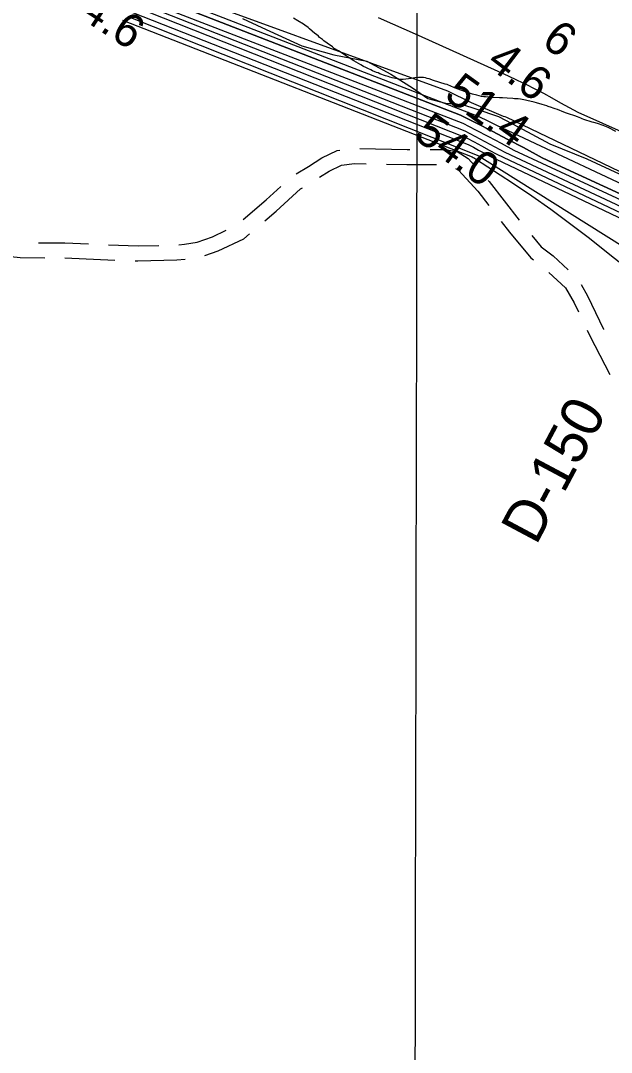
# Model space of a CAD drawing. Extents: x 3192986 to 3230865, y 867483 to 892886.
# Drawn here: x 3212086 to 3213265, y 874442 to 876501 of the extents above; entities that cross this region are included whole.
import ezdxf

# ---------------------------------------------------------------- set-up
doc = ezdxf.new("R2010")
doc.units = 0
for name, color, linetype in [('V-GRID-MAJR', 7, 'Continuous'), ('V-RIVR-EDGE', 7, 'Continuous'), ('V-RIVR-RANG', 7, 'Continuous'), ('V-RIVR-RANG-IDEN', 7, 'Continuous'), ('V-ROAD-CNTR', 7, 'Continuous'), ('V-SITE-VEGE', 7, 'Continuous'), ('V-TOPO-DPTH', 7, 'Continuous'), ('V-TOPO-MAJR', 7, 'Continuous'), ('V-TOPO-MINR', 7, 'Continuous'), ('V-TOPO-WATR', 7, 'Continuous')]:
    doc.layers.add(name, color=color, linetype=linetype)

msp = doc.modelspace()

# ---------------------------------------------------------------- linework, layer by layer
at = {"layer": 'V-GRID-MAJR'}
msp.add_spline([(3212870.4, 872891.2), (3212881.9, 878950.4), (3212893.3, 885013.1), (3212904.8, 891075.8), (3212904.8, 891079.2)], degree=3, dxfattribs=at)
at = {"layer": 'V-RIVR-EDGE'}
msp.add_lwpolyline([(3212528.3, 876504.7), (3212567.4, 876487.2), (3212646.8, 876450.5), (3212710.7, 876432.6), (3212776.7, 876420.2), (3212824.9, 876394), (3212867.9, 876366.5), (3212898.7, 876345.1), (3212933.9, 876336.4), (3212967.3, 876333.7), (3212994.3, 876324.9), (3213039.4, 876309.2), (3213078.5, 876288.6), (3213141.9, 876254.6), (3213215.7, 876224.8), (3213280, 876195.1)], dxfattribs=at)
at = {"layer": 'V-ROAD-CNTR'}
msp.add_line((3212174.2, 876027.3), (3212274.1, 876023.1), dxfattribs=at)
for points in [[(3212635.7, 876194.9), (3212660.3, 876209.8), (3212686.8, 876226.8), (3212717.7, 876241.9), (3212723, 876242.5)], [(3212762.8, 876245.4), (3212856.9, 876243.4), (3212862.8, 876243.4)], [(3212902.8, 876243.7), (3212931.7, 876243.8), (3212957.2, 876239.6), (3212979, 876225.5), (3212992.1, 876211.3)], [(3212682.2, 876188.2), (3212701.5, 876200.6), (3212726.2, 876212.6), (3212752.4, 876215.6), (3212775.6, 876215.1)], [(3212815.6, 876214.3), (3212856.7, 876213.4), (3212915.6, 876213.7)], [(3212953.9, 876206), (3212959.6, 876202.3), (3212998.2, 876160.3), (3213020.3, 876131.7)], [(3213019.1, 876181.8), (3213021.1, 876179.7), (3213080.5, 876102.9)], [(3212529.6, 876103.8), (3212575.6, 876143.1), (3212604.8, 876169.7)], [(3212573, 876101.4), (3212595.5, 876120.6), (3212644, 876164.8), (3212648.1, 876167.3)], [(3213044.8, 876100.1), (3213061.2, 876078.9), (3213103.9, 876027.5), (3213109, 876023.7)], [(3212401.3, 876053.7), (3212412.6, 876054.6), (3212437.8, 876058.7), (3212468.5, 876069.3), (3212496.2, 876082.4)], [(3212453.1, 876032.2), (3212479.9, 876041.5), (3212531, 876065.6), (3212542.6, 876075.5)], [(3213105.9, 876072), (3213124.7, 876049.4), (3213148.6, 876031.4), (3213178.5, 876003.8)], [(3212121.5, 876057.7), (3212173.9, 876057.3), (3212221.5, 876055.4)], [(3212261.4, 876053.7), (3212320.3, 876051.2), (3212361.4, 876052.3)], [(3212034.5, 876033.1), (3212085, 876027.9), (3212134.2, 876027.6)], [(3212314.1, 876021.5), (3212320, 876021.2), (3212397.2, 876023.2), (3212414, 876024.7)], [(3213140, 875998.5), (3213173.3, 875967.7), (3213190.5, 875937.4), (3213199, 875919.6)], [(3213204.3, 875973.9), (3213217.2, 875951.3), (3213248.8, 875884.8), (3213249, 875884.5)], [(3213216.2, 875883.4), (3213222, 875871.5), (3213261.9, 875794.5)]]:
    msp.add_lwpolyline(points, dxfattribs=at)
at = {"layer": 'V-SITE-VEGE'}
for p, q in [((3212639.1, 876500.7), (3212630.2, 876505.5)), ((3212650.6, 876493.6), (3212639.1, 876500.7)), ((3212653.2, 876491.6), (3212650.6, 876493.6)), ((3212659.5, 876487.1), (3212653.2, 876491.6)), ((3212662.5, 876484.7), (3212659.5, 876487.1)), ((3212673.2, 876475.4), (3212662.5, 876484.7)), ((3212676.1, 876473), (3212673.2, 876475.4)), ((3212680.1, 876469.6), (3212676.1, 876473)), ((3212682.5, 876467.4), (3212680.1, 876469.6)), ((3212688.4, 876462.9), (3212682.5, 876467.4)), ((3212690.8, 876460.7), (3212688.4, 876462.9)), ((3212697.3, 876456), (3212690.8, 876460.7)), ((3212700.5, 876454), (3212697.3, 876456)), ((3212703.5, 876451.6), (3212700.5, 876454)), ((3212708, 876448.2), (3212703.5, 876451.6)), ((3212711.4, 876445.4), (3212708, 876448.2)), ((3212719.9, 876440.3), (3212711.4, 876445.4)), ((3212741.5, 876426.6), (3212719.9, 876440.3)), ((3212750.6, 876420.7), (3212741.5, 876426.6)), ((3212764.5, 876412.4), (3212750.6, 876420.7)), ((3212770.2, 876409.4), (3212764.5, 876412.4)), ((3212774.6, 876407.4), (3212770.2, 876409.4)), ((3212778.9, 876405.2), (3212774.6, 876407.4)), ((3212784.9, 876402.7), (3212778.9, 876405.2)), ((3212788.2, 876400.9), (3212784.9, 876402.7)), ((3212796.1, 876397.5), (3212788.2, 876400.9)), ((3212799.3, 876396.3), (3212796.1, 876397.5)), ((3212802.3, 876394.9), (3212799.3, 876396.3)), ((3212814, 876390.6), (3212802.3, 876394.9)), ((3212819.3, 876389.2), (3212814, 876390.6)), ((3212822.7, 876388), (3212819.3, 876389.2)), ((3212827, 876386.8), (3212822.7, 876388)), ((3212837.1, 876384.4), (3212827, 876386.8)), ((3212840.5, 876384), (3212837.1, 876384.4)), ((3212845.5, 876383.6), (3212840.5, 876384)), ((3212849.4, 876383.6), (3212845.5, 876383.6)), ((3212854.8, 876384), (3212849.4, 876383.6)), ((3212865.1, 876385), (3212854.8, 876384)), ((3212872.8, 876386.4), (3212865.1, 876385)), ((3212879.7, 876387.4), (3212872.8, 876386.4)), ((3212884.7, 876387.4), (3212879.7, 876387.4)), ((3212890, 876387), (3212884.7, 876387.4)), ((3212893.6, 876386.4), (3212890, 876387)), ((3212896.9, 876385.6), (3212893.6, 876386.4)), ((3212901.1, 876384.4), (3212896.9, 876385.6)), ((3212910, 876381.6), (3212901.1, 876384.4)), ((3212933, 876374.1), (3212910, 876381.6)), ((3212937, 876373.1), (3212933, 876374.1)), ((3212945.7, 876369.4), (3212937, 876373.1)), ((3212948.8, 876368.2), (3212945.7, 876369.4)), ((3212951.8, 876366.8), (3212948.8, 876368.2)), ((3212958.9, 876364), (3212951.8, 876366.8)), ((3212962.1, 876363), (3212958.9, 876364)), ((3212966.5, 876361.2), (3212962.1, 876363)), ((3212971.8, 876359.3), (3212966.5, 876361.2)), ((3212983.5, 876355.5), (3212971.8, 876359.3)), ((3212987.6, 876354.3), (3212983.5, 876355.5)), ((3212996.2, 876352.3), (3212987.6, 876354.3)), ((3213005.3, 876349.6), (3212996.2, 876352.3)), ((3213010, 876349), (3213005.3, 876349.6)), ((3213013.4, 876348.4), (3213010, 876349)), ((3213024.9, 876347.4), (3213013.4, 876348.4)), ((3213041.1, 876347), (3213024.9, 876347.4)), ((3213047.5, 876346.6), (3213041.1, 876347)), ((3213056.6, 876346.2), (3213047.5, 876346.6)), ((3213068.1, 876345.2), (3213056.6, 876346.2)), ((3213071.6, 876345), (3213068.1, 876345.2)), ((3213075.4, 876344.6), (3213071.6, 876345)), ((3213078.7, 876344.4), (3213075.4, 876344.6)), ((3213083.5, 876343.8), (3213078.7, 876344.4)), ((3213086.9, 876343.2), (3213083.5, 876343.8)), ((3213090, 876342.8), (3213086.9, 876343.2)), ((3213093.2, 876342.2), (3213090, 876342.8)), ((3213098.6, 876340.8), (3213093.2, 876342.2)), ((3213101.7, 876340.2), (3213098.6, 876340.8)), ((3213110.8, 876337.9), (3213101.7, 876340.2)), ((3213115.2, 876336.5), (3213110.8, 876337.9)), ((3213126.5, 876333.5), (3213115.2, 876336.5)), ((3213135.6, 876330.7), (3213126.5, 876333.5)), ((3213138.4, 876329.5), (3213135.6, 876330.7)), ((3213145.1, 876327.3), (3213138.4, 876329.5)), ((3213148.7, 876325.8), (3213145.1, 876327.3)), ((3213152.8, 876324.6), (3213148.7, 876325.8)), ((3213157.2, 876323.2), (3213152.8, 876324.6)), ((3213169.6, 876318.2), (3213157.2, 876323.2)), ((3213175, 876316.3), (3213169.6, 876318.2)), ((3213183.3, 876313.5), (3213175, 876316.3)), ((3213187.7, 876311.9), (3213183.3, 876313.5)), ((3213191.8, 876310.7), (3213187.7, 876311.9)), ((3213197.2, 876308.7), (3213191.8, 876310.7)), ((3213203.9, 876306), (3213197.2, 876308.7)), ((3213206.7, 876304.6), (3213203.9, 876306)), ((3213210, 876303.8), (3213206.7, 876304.6)), ((3213213.4, 876302.4), (3213210, 876303.8)), ((3213222.5, 876299.2), (3213213.4, 876302.4)), ((3213226.5, 876298.2), (3213222.5, 876299.2)), ((3213229.8, 876297.2), (3213226.5, 876298.2)), ((3213237.2, 876295.4), (3213229.8, 876297.2)), ((3213248.5, 876291.5), (3213237.2, 876295.4)), ((3213251.8, 876289.9), (3213248.5, 876291.5)), ((3213258.4, 876287.3), (3213251.8, 876289.9)), ((3213273.6, 876279.8), (3213258.4, 876287.3))]:
    msp.add_line(p, q, dxfattribs=at)
at = {"layer": 'V-TOPO-DPTH'}
for points in [[(3212338.1, 876579.4), (3212937.6, 876360.4), (3212953.4, 876353), (3212969.2, 876345.4), (3212985, 876337.6), (3213048.6, 876310.2), (3213052.1, 876309.2), (3213055.7, 876308), (3213713.4, 875992.7), (3213733.7, 875981.1), (3213753.9, 875969.3), (3214479.8, 875710.7), (3214498.5, 875702.9), (3214517.2, 875694.9), (3214526.6, 875691), (3214536, 875687.1), (3214545.4, 875683.5), (3215340.9, 875516.3)], [(3212338.1, 876579.4), (3212937.6, 876360.4), (3212953.4, 876353), (3212969.2, 876345.4), (3212985, 876337.6), (3213048.6, 876310.2), (3213052.1, 876309.2), (3213055.7, 876308), (3213713.4, 875992.7), (3213733.7, 875981.1), (3213753.9, 875969.3), (3214479.8, 875710.7), (3214498.5, 875702.9), (3214517.2, 875694.9), (3214526.6, 875691), (3214536, 875687.1), (3214545.4, 875683.5), (3215340.9, 875516.3)], [(3213712.7, 875956.8), (3213147.7, 876216.8), (3213126.9, 876227.3), (3213089.6, 876247.3), (3213058.3, 876263.8), (3213027, 876280.2), (3212995.5, 876296.2), (3212963.9, 876312.1), (3212347.9, 876551.7)]]:
    msp.add_lwpolyline(points, dxfattribs=at)
at = {"layer": 'V-TOPO-MAJR'}
msp.add_lwpolyline([(3212338, 876518.7), (3212975.6, 876266.9), (3212990.7, 876258.9), (3213005.8, 876250.9), (3213020.9, 876242.6), (3213035.9, 876234.3), (3213706.5, 875917.2)], dxfattribs=at)
at = {"layer": 'V-TOPO-MINR'}
for points in [[(3212331.2, 876569), (3213000.4, 876309.4), (3213017.9, 876300.8), (3213035.5, 876292), (3213715.1, 875972.6)], [(3212316.4, 876548.1), (3212968.2, 876295.9), (3212993.8, 876282.9), (3213019.4, 876269.6), (3213044.8, 876256.1), (3213070.1, 876242.5), (3213694.5, 875952)], [(3212347.9, 876551.7), (3212963.9, 876312.1), (3212995.5, 876296.2), (3213027, 876280.2), (3213058.3, 876263.8), (3213089.6, 876247.3), (3213126.9, 876227.3), (3213147.7, 876216.8), (3213712.7, 875956.8)], [(3212330.3, 876533.1), (3212972, 876280.9), (3212992.2, 876270.5), (3213012.3, 876259.9), (3213032.4, 876249.1), (3213052.3, 876238.2), (3213697.9, 875935.6)], [(3212305.1, 876507.2), (3213000.3, 876231), (3213006.3, 876227.3), (3213609.8, 875848.6)], [(3212307.5, 876517.8), (3212978.8, 876253.8), (3212989.3, 876248.2), (3212999.8, 876242.5), (3213010.3, 876236.7), (3213020.7, 876230.8), (3213667.3, 875923.8)], [(3212799, 876507), (3212879, 876472), (3213058.9, 876390.6), (3213076.7, 876382.3), (3213094.3, 876373.8), (3213111.7, 876364.9), (3213129, 876355.7), (3213146.2, 876346.4), (3213163.3, 876337), (3213180.5, 876327.6), (3213197.6, 876318.1), (3213831.6, 876035.1)], [(3212289, 876501.9), (3212986.7, 876228.9), (3212989, 876227.5), (3212991.3, 876226.1), (3212993.6, 876224.7), (3213067.2, 876177), (3213105.8, 876151.2), (3213143.9, 876124.6), (3213181.3, 876096.9), (3213218.1, 876068.5), (3213579.4, 875780.9)]]:
    msp.add_lwpolyline(points, dxfattribs=at)
at = {"layer": 'V-TOPO-WATR'}
msp.add_lwpolyline([(3212338.1, 876579.4), (3212937.6, 876360.4), (3212953.4, 876353), (3212969.2, 876345.4), (3212985, 876337.6), (3213048.6, 876310.2), (3213052.1, 876309.2), (3213055.7, 876308), (3213713.4, 875992.7), (3213733.7, 875981.1), (3213753.9, 875969.3), (3214479.8, 875710.7), (3214498.5, 875702.9), (3214517.2, 875694.9), (3214526.6, 875691), (3214536, 875687.1), (3214545.4, 875683.5), (3215340.9, 875516.3)], dxfattribs=at)

# ---------------------------------------------------------------- texts
at = {"layer": 'V-RIVR-RANG'}
for s, rotation, p in [('54.6', 326.7983, (3212158.2, 876536.1)), ('6', 322.6021, (3213122.5, 876454.2)), ('4.6', 322.6021, (3213013, 876412.1)), ('51.4', 324.1583, (3212928.5, 876346.8)), ('54.0', 324.1583, (3212867.8, 876267.3))]:
    msp.add_text(s, height=67, rotation=rotation, dxfattribs=at).set_placement(p)
at = {"layer": 'V-RIVR-RANG-IDEN'}
msp.add_text('D-150', height=83, rotation=61.9611, dxfattribs=at).set_placement((3213114.4, 875451.9))

doc.saveas('drawing.dxf')
